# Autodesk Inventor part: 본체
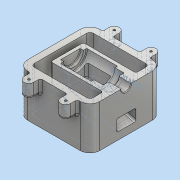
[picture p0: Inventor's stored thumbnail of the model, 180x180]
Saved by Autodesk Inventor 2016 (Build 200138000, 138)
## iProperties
Created: 2018-01
Part Number: 본체
Material: 알루미늄 6061
Document SubType Name: Modeling
Designer: Administrator
Density: 2.7 g/cm^3
Appearance: 알루미늄 - 평지
Mass: 995.304 g
Surface Area: 835.211 cm^2
Volume: 368.631 cm^3
Author: Administrator
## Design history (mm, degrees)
sketch "스케치4"
  geometry: L1 (-55, 55)-(55, 55); L2 (55, 55)-(55, -55); L3 (55, -55)-(-55, -55); L4 (-55, -55)-(-55, 55); L5 (-55, 55)-(55, -55); L6 (55, 55)-(-55, -55); L7 (45, 45)-(-45, 45); L8 (-45, 45)-(-45, -45); L9 (-45, -45)-(45, -45); L10 (45, -45)-(45, 45); 3 further points
  constraints: 20 end point, 2 midpoint, 2 parallel, 2 point on line, 1 horizontal, 1 perpendicular
  dimensions: "d17" = 110 distance of L1.end L2.end; "d18" = 110 distance of L1.start L1.end; "d19" = 90 distance of L9.end L7.start; "d20" = 10 distance between parallel lines of L2 L10; "d21" = 10 distance between parallel lines of L1 L7; "d22" = 10 distance between parallel lines of L4 L8; "d23" = 90 distance of L8.end L9.end
extrude "돌출2" new body sketch "스케치4" distance "d27" = 65; taper "d28" = 0 deg
sketch "스케치5"
  geometry: L1 (-45, -45)-(-45, 45) reference; L2 (-45, 45)-(45, 45) reference; L3 (45, 45)-(45, -45) reference; L4 (45, -45)-(-45, -45) reference; L5 (-55, 55)-(-55, -55) reference; L6 (-55, -55)-(55, -55) reference; L7 (55, -55)-(55, 55) reference; L8 (55, 55)-(-55, 55) reference; L9 (-55, 55)-(55, 55) reference; 1 further point
node "작업 평면1"
sketch "스케치6"
  geometry: L1 (-55, 55)-(55, 55) reference; L2 (-35.5, 65)-(-20.5, 65); L3 (-20.5, 65)-(-20.5, 55); L4 (-20.5, 55)-(-35.5, 55); L5 (-35.5, 55)-(-35.5, 65); L6 (-55, 55)-(-55, -55) reference; A1 r 7.5 centre (-28, 65) between (-20.5, 65) and (-35.5, 65); 1 further point
  constraints: 8 end point, 2 parallel, 2 point on circle, 1 centre point, 1 horizontal, 1 perpendicular, 1 point on line, 1 tangent
  dimensions: "d30" = 7.5 radius of A1; "d31" = 27 distance from line of L6 A1.centre; "d32" = 10 distance from line of A1.centre L1
extrude "돌출3" join sketch "스케치6" distance "d33" = 20; taper "d34" = 0 deg
sketch "스케치8"
  geometry: L1 (110, -65)-(110, 0) reference; L2 (0, 0)-(110, 0) reference; 2 further points
  constraints: 1 other
  dimensions: "d38" = 20 distance from line of L2 point (55, -20); "d39" = 55 distance from line of L1 point (55, -20)
feature "엠보싱1" sketch "스케치8" dims "d17" = 110, "d18" = 110, "d19" = 90, "d20" = 10, "d21" = 10, "d22" = 10, "d23" = 90, "d40" = 0.5, "d41" = 0
hole "구멍1" diameter "d44" = 3.242; stored, may be unused: countersink angle "d48" = 90 deg, drill point angle "d50" = 118 deg; dims "d42" = 10, "d43" = 10, "d45" = 9, "d46" = 4, "d47" = 2, "d49" = 11
sketch "스케치10"
  geometry: L1 (-45, -65)-(-45, -56.436); L2 (-45, -56.436)-(35, -35); L3 (35, -35)-(35, 0); L4 (-45, 0)-(45, 0) reference; L5 (45, -65)-(-45, -65) reference; L6 (55, 0)-(55, -65) reference; L7 (35, 0)-(-45, 0); L8 (-35.5, 0)-(-55, 0) reference; L9 (-45, 0)-(-45, -65) reference; L10 (-45, -65)-(-45, -65); L11 (-45, 0)-(-45, -65) reference; L12 (-45, 0)-(-45, -56.436); 2 further points
  constraints: 12 end point, 3 collinear, 3 point on line, 1 midpoint, 1 parallel, 1 vertical
  dimensions: "d51" = 105 deg angle of L1 L2; "d52" = 30 distance from line of L5 L2.end; "d53" = 20 distance between parallel lines of L6 L3
extrude "돌출4" join sketch "스케치10" stored distance "d54" = 50; taper "d55" = 0 deg
sketch "스케치12" dims "d94" = 3
  geometry: L1 (-45, 0)-(-45, -65) reference; L2 (-45, -56.436)-(35, -35) reference; L3 (35, -35)-(35, 0) reference; L4 (-58.442, 0)-(50.741, 0); L5 (-55, -7.5)-(-36, -7.5); L6 (-36, -7.5)-(-36, -16); L7 (-36, -16)-(-22, -16); L8 (-22, -16)-(-22, -20); L9 (-22, -20)-(25, -20); L10 (25, -20)-(25, -15); L11 (25, -15)-(30, -15); L12 (30, -15)-(30, 0); L13 (35, 0)-(-45, 0) reference; L14 (-55, 0)-(-55, -65) reference; L15 (-55, -7.5)-(-55, 0); L16 (30, 0)-(-55, 0); 2 further points
  constraints: 22 end point, 5 perpendicular, 3 point on line, 2 collinear, 2 horizontal, 2 vertical, 1 midpoint
  dimensions: "d56" = 15 diameter of L5 L4; "d57" = 32 diameter of L7 L4; "d59" = 40 diameter of L9 L4; "d60" = 30 diameter of L11 L4; "d61" = 19 distance of L5.start L5.end; "d62" = 14 distance of L6.end L7.end; "d63" = 47 distance of L8.end L9.end; "d64" = 5 distance of L10.end L11.end
revolve "회전1" sketch "스케치12" stored, may be unused: angle "d65" = 90 deg
sketch "스케치13"
  geometry: L1 (25, -20)-(-22, -20) reference; L2 (-17, -20)-(-17, -25.757); L3 (-17, -25.757)-(-55, -35.939); L4 (20, -20)-(20, -33.843); L5 (20, -33.843)-(-55, -53.939); L6 (35, -35)-(-45, -56.436) reference; L7 (-55, 0)-(-55, -65) reference; L8 (25, 0)-(25, -20) reference; L9 (-22, 0)-(-22, -20) reference; L10 (-17, -20)-(20, -20); L11 (20.5, -20)-(20.5, 0) reference; 1 further point
  constraints: 10 end point, 4 point on line, 2 parallel, 2 vertical, 1 perpendicular
  dimensions: "d66" = 5 distance between parallel lines of L6 L5; "d67" = 37 distance between parallel lines of L4 L2; "d68" = 18 distance of L5.end L3.end; "d71" = 5 distance between parallel lines of L9 L2
extrude "돌출5" cut sketch "스케치13" stored distance "d72" = 30; taper "d73" = 0 deg
sketch "스케치15"
  geometry: L1 (-20, 15)-(17, 15); L2 (17, 15)-(17, -15); L3 (17, -15)-(-20, -15); L4 (-20, -15)-(-20, 15); L5 (36, -7.5)-(36, 7.5) reference; L6 (22, -16)-(22, 16) reference; L7 (-25, -15)-(-25, 15) reference; 3 further points
  constraints: 8 end point, 2 midpoint, 2 parallel, 1 horizontal, 1 horizontal alignment, 1 perpendicular
  dimensions: "d98" = 37 distance of L1.start L1.end; "d100" = 30 distance of L1.end L2.end; "d101" = 5 distance between parallel lines of L6 L2
extrude "돌출6" cut sketch "스케치15" distance "d76" = 21; taper "d77" = 0 deg
fillet "모깎기1" dims "d78" = 15
fillet "모깎기2" dims "d79" = 5
fillet "모깎기3" dims "d80" = 3
fillet "모깎기4" dims "d81" = 3
fillet "모깎기5" dims "d82" = 3
fillet "모깎기6" dims "d83" = 3
fillet "모깎기7" dims "d84" = 3
chamfer "모따기1" distance "d85" = 1; stored, may be unused: second distance "d86" = 2, angle "d87" = 45 deg
chamfer "모따기2" distance "d88" = 1; stored, may be unused: second distance "d89" = 2, angle "d90" = 45 deg
fillet "모깎기8" dims "d94" = 3
fillet "모깎기9" dims "d102" = 3
fillet "모깎기10" dims "d103" = 1
node "솔리드2"
pattern_linear "직사각형 패턴1" dims "d37" = 56
mirror "대칭1"
mirror "대칭2"
mirror "대칭3"
